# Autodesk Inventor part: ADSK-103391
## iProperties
Shininess: 0.0
Created: 2000-12
Part Number: ADSK-103391
Document SubType Name: Modeling
Stock Number: ADSK-103391
Density: 1 g/cm^3
Density: 0.0
Volumn: 0.0
Area: 0.0
PropertySet Name: Model Information
Control State: 0
Master: False
Checked Out: False
Author: gao
